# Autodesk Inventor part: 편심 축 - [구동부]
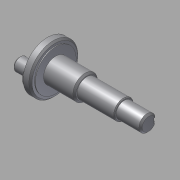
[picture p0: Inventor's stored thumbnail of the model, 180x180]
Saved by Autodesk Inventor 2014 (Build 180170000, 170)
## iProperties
Created: 2015-10
Part Number: 편심 축 - [구동부]
Document SubType Name: Modeling
Designer: mdu
Density: 7.86 g/cm^3
Material: 강철, 연강
Mass: 86.2323 g
Surface Area: 42.7652 cm^2
Volume: 10.971 cm^3
Appearance: 기본값
Author: mdu
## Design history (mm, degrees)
sketch "스케치1"
  geometry: L1 (1.75, -12.001)-(1.75, 11.999) reference; L2 (-16.95, -14)-(-16.95, 14) reference; L3 (-36.25, -18.06)-(-36.25, 18.06) reference; L4 (-41.25, 0)-(20.75, 0); L5 (-41.25, 0)-(-41.25, 15); L6 (-41.25, 15)-(-36.25, 15); L7 (-36.25, 15)-(-36.25, 7.5); L8 (-36.25, 7.5)-(-17.25, 7.5); L9 (-17.25, 6)-(5.75, 6); L10 (20.75, 5)-(20.75, 0); L11 (5.75, 6)-(5.75, 5); L12 (5.75, 5)-(20.75, 5); L13 (-17.25, -13.7)-(-17.25, 13.7) reference; L14 (-17.25, 7.5)-(-17.25, 6); 2 further points
  constraints: 20 end point, 7 perpendicular, 5 point on line, 1 collinear, 1 midpoint, 1 parallel
  dimensions: "d0" = 12 diameter of L9 L4; "d1" = 15 diameter of L8 L4; "d2" = 30 diameter of L6 L4; "d3" = 5 distance of L5.end L6.end; "d4" = 62 distance of L4.start L4.end; "d5" = 10 diameter of L12 L4; "d6" = 15 distance of L11.end L10.start
revolve "회전1" sketch "스케치1" stored, may be unused: angle "d7" = 90 deg
sketch "스케치4"
  geometry: C1 r 15 at (0, 0) reference; C2 r 12.5 at (0, 0); 1 further point
  constraints: 1 centre point, 1 coincident
  dimensions: "d24" = 25 diameter of C2
extrude "돌출4" cut sketch "스케치4" distance "d25" = 0.5; taper "d26" = 0 deg
sketch "스케치2"
  geometry: C1 r 4 at (0, -7.5); C2 r 7.5 at (0, -7.5); C3 r 15 at (0, 0) reference; 1 further point
  constraints: 2 centre point, 1 coincident, 1 tangent, 1 vertical alignment
  dimensions: "d8" = 8 diameter of C1; "d9" = 7.5 distance of point (0, 0) C1.centre
extrude "돌출1" join sketch "스케치2" distance "d10" = 10; taper "d11" = 0 deg
extrude "돌출2" join sketch "스케치2" distance "d12" = 0.5; taper "d13" = 0 deg
node "작업 평면1"
sketch "스케치3"
  geometry: L1 (-7.5, 5)-(-7.5, -5) reference; L2 (-7.5, 1.5)-(3, 1.5); L3 (3, -1.5)-(-7.5, -1.5); A1 r 1.5 centre (3, 0) between (3, -1.5) and (3, 1.5); 2 further points
  constraints: 4 end point, 2 perpendicular, 2 point on circle, 2 point on line, 2 tangent, 1 centre point, 1 horizontal alignment, 1 midpoint
  dimensions: "d14" = 3 distance between parallel lines of L3 L2; "d15" = 12 dimension on A1 L1
extrude "돌출3" cut sketch "스케치3" distance "d16" = 1.8; taper "d17" = 0 deg
chamfer "모따기1" distance "d18" = 1; stored, may be unused: second distance "d19" = 2, angle "d20" = 45 deg
chamfer "모따기2" distance "d21" = 0.5; stored, may be unused: second distance "d22" = 2, angle "d23" = 45 deg
node "솔리드1"
node "참조1"
node "참조2"
node "참조3"
node "참조4"
